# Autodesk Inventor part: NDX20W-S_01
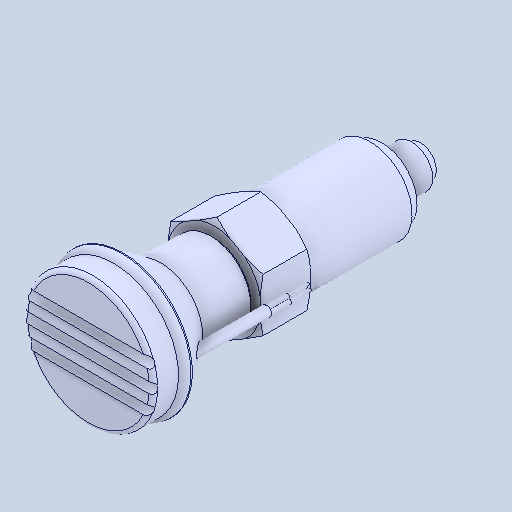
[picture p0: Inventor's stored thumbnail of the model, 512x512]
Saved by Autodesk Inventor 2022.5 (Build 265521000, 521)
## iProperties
Created: 2024-05
Part Number: NDX20W-S_01
Material: 一般
Document SubType Name: Modeling
Designer: ImaoCorp
Density: 1 g/cm^3
Appearance: 既定
Author: ImaoCorp
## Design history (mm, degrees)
feature "NDX20W-S_01"
node "ソリッド1"
